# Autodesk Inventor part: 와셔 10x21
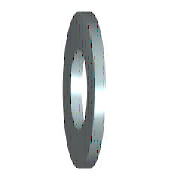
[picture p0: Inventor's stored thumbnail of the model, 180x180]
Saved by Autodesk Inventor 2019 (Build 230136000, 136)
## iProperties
Created: 2012-02
Part Number: 와셔 10x21
Material: 강철, 연강
Description: 평면 와셔
Document SubType Name: Modeling
Standard: KS B 1326
Designer: mduedu
Standards Organization: KS
Language: ko-KR
Size Designation: 10x21
Categories: <MemberInstance><Categories><Category DisplayName="조임쇠" InternalName="e4da775c-781d-43d5-af7c-5136215cf5a6" Mnemonic="FSTN"><Category DisplayName="와셔" InternalN
Density: 1 g/cm^3
Appearance: 파란색 - 벽 페인트 - 광택
IsCustomPart: 1
Author: mduedu
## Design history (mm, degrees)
sketch "스케치"
  geometry: C1 r 10.5 at (0, 0); C2 r 5.25 at (0, 0); 1 further point
  constraints: 2 centre point, 2 coincident
  dimensions: "d0" = 10.5 diameter of C2 (= SD1); "d1" = 21 diameter of C1 (= SD2)
extrude "본체" new body sketch "스케치" distance "d2" = 2 (= SD); taper "d3" = 0 deg
workaxis "Work Axis1"
workplane "Work Plane1"
body "Solid1"
other parameters: "SD1" = 10.5 [user parameter; used in 1 equation term], "SD2" = 21 [user parameter; used in 1 equation term], "SD" = 2 [user parameter; used in 1 equation term], "d4" = 0, "d5" = 0, "d6" = 0, "d7" = 0
